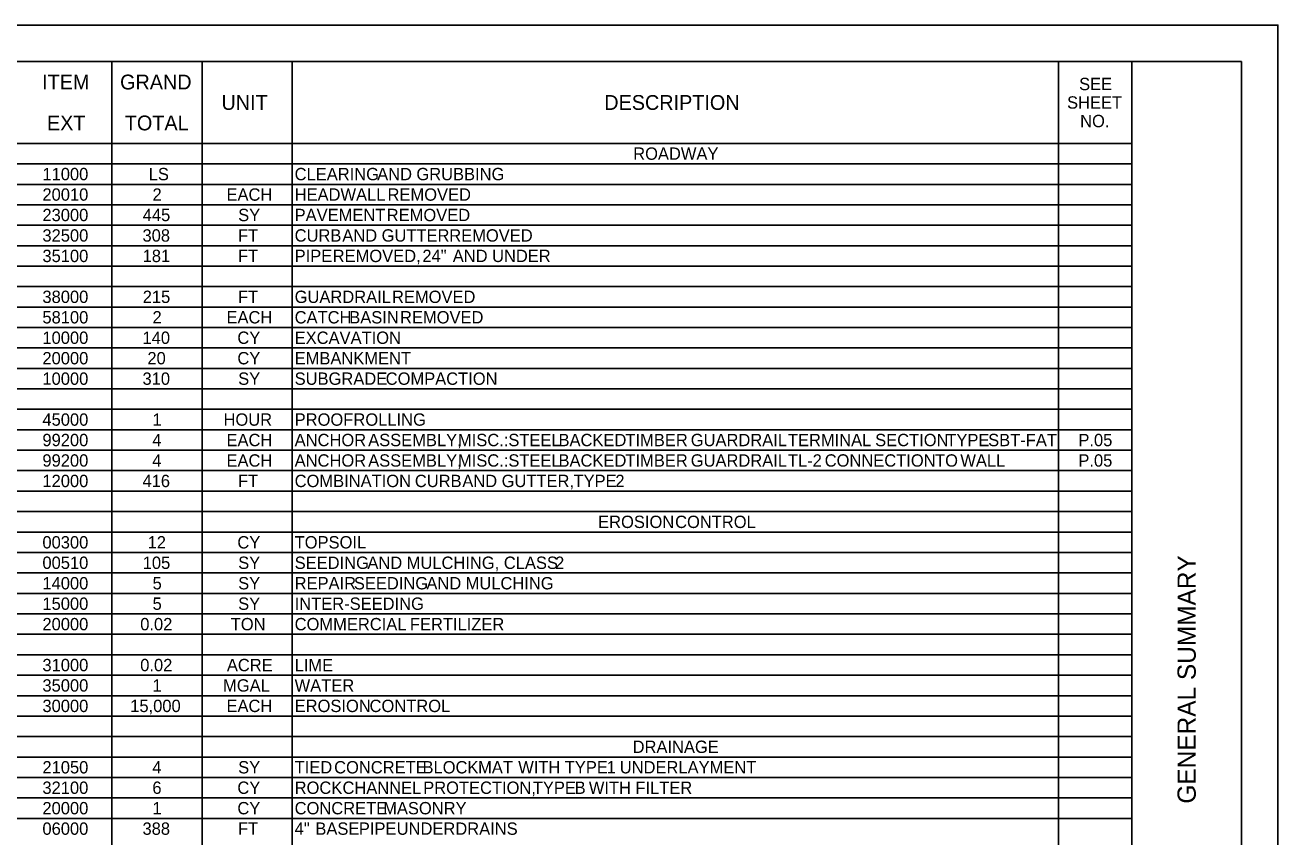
# Model space of a CAD drawing. Extents: x 0 to 34, y 0 to 22.
# Drawn here: x 16.85 to 34, y 10.89 to 22 of the extents above; entities that cross this region are included whole.
import ezdxf

# ---------------------------------------------------------------- set-up
doc = ezdxf.new("R2010")
doc.units = 0
for name, color, linetype in [('SH_Border', 7, 'Continuous'), ('SH_Cut_Line', 7, 'Continuous'), ('SH_Data', 7, 'Continuous')]:
    doc.layers.add(name, color=color, linetype=linetype)

msp = doc.modelspace()

# ---------------------------------------------------------------- linework, layer by layer
at = {"layer": 'SH_Border'}
msp.add_line((32, 0.5), (32, 21.5), dxfattribs=at)
msp.add_lwpolyline([(1.5, 21.5), (33.5, 21.5), (33.5, 0.5), (1.5, 0.5)], close=True, dxfattribs=at)
at = {"layer": 'SH_Cut_Line'}
msp.add_lwpolyline([(0, 0), (34, 0), (34, 22), (0, 22)], close=True, dxfattribs=at)
at = {"layer": 'SH_Data'}
for p, q in [((16.799, 21.5), (19.27, 21.5)), ((18.035, 0.502), (18.035, 21.5)), ((19.27, 21.5), (20.505, 21.5)), ((19.27, 0.502), (19.27, 21.5)), ((20.505, 21.5), (30.995, 21.5)), ((20.505, 0.502), (20.505, 21.5)), ((30.995, 21.5), (32, 21.5)), ((30.995, 0.502), (30.995, 21.5)), ((32, 0.502), (32, 21.5)), ((13.555, 20.38), (32, 20.38)), ((19.27, 20.38), (32, 20.38)), ((1.5, 20.1), (32, 20.1)), ((1.5, 19.82), (32, 19.82)), ((1.5, 19.54), (32, 19.54)), ((1.5, 19.26), (32, 19.26)), ((1.5, 18.98), (32, 18.98)), ((1.5, 18.7), (32, 18.7)), ((1.5, 18.42), (32, 18.42)), ((1.5, 18.14), (32, 18.14)), ((1.5, 17.86), (32, 17.86)), ((1.5, 17.58), (32, 17.58)), ((1.5, 17.3), (32, 17.3)), ((1.5, 17.021), (32, 17.021)), ((1.5, 16.741), (32, 16.741)), ((1.5, 16.461), (32, 16.461)), ((1.5, 16.181), (32, 16.181)), ((1.5, 15.901), (32, 15.901)), ((1.5, 15.621), (32, 15.621)), ((1.5, 15.341), (32, 15.341)), ((1.5, 15.061), (32, 15.061)), ((1.5, 14.781), (32, 14.781)), ((1.5, 14.501), (32, 14.501)), ((1.5, 14.221), (32, 14.221)), ((1.5, 13.941), (32, 13.941)), ((1.5, 13.661), (32, 13.661)), ((1.5, 13.381), (32, 13.381)), ((1.5, 13.101), (32, 13.101)), ((1.5, 12.821), (32, 12.821)), ((1.5, 12.541), (32, 12.541)), ((1.5, 12.261), (32, 12.261)), ((1.5, 11.981), (32, 11.981)), ((1.5, 11.701), (32, 11.701)), ((1.5, 11.421), (32, 11.421)), ((1.5, 11.141), (32, 11.141))]:
    msp.add_line(p, q, dxfattribs=at)

# ---------------------------------------------------------------- texts
for s, height, p in [('ITEM', 0.2027, (17.081, 21.119)), ('GRAND', 0.2027, (18.148, 21.119)), ('SEE', 0.1689, (31.278, 21.109)), ('UNIT', 0.2027, (19.536, 20.839)), ('DESCRIPTION', 0.20269, (24.777, 20.839)), ('SHEET', 0.1689, (31.113, 20.856)), ('EXT', 0.2027, (17.147, 20.559)), ('TOTAL', 0.2027, (18.213, 20.559)), ('NO.', 0.1689, (31.292, 20.602)), ('ROADWAY', 0.1689, (25.173, 20.156)), ('11000', 0.1689, (17.085, 19.876)), ('LS', 0.1689, (18.54, 19.876)), ('CLEARING', 0.1689, (20.538, 19.876)), (' AND', 0.1689, (21.605, 19.876)), (' GRUBBING', 0.1689, (22.142, 19.876)), ('20010', 0.1689, (17.085, 19.596)), ('2', 0.169, (18.592, 19.596)), ('EACH', 0.1689, (19.605, 19.596)), ('HEADWALL', 0.1689, (20.538, 19.596)), (' REMOVED', 0.1689, (21.747, 19.596)), ('23000', 0.1689, (17.085, 19.316)), ('445', 0.1689, (18.458, 19.316)), ('SY', 0.1689, (19.765, 19.316)), ('PAVEMENT', 0.1689, (20.538, 19.316)), (' REMOVED', 0.1689, (21.736, 19.316)), ('32500', 0.1689, (17.085, 19.036)), ('308', 0.1689, (18.455, 19.036)), ('FT', 0.1689, (19.762, 19.036)), ('CURB', 0.1689, (20.538, 19.036)), (' AND', 0.1689, (21.128, 19.036)), (' GUTTER', 0.1689, (21.666, 19.036)), (' REMOVED', 0.1689, (22.592, 19.036)), ('35100', 0.1689, (17.085, 18.756)), ('181', 0.1689, (18.457, 18.756)), ('FT', 0.1689, (19.762, 18.756)), ('PIPE', 0.1689, (20.538, 18.756)), (' REMOVED,', 0.1689, (20.996, 18.756)), (' 24"', 0.1689, (22.224, 18.756)), (' AND', 0.1689, (22.64, 18.756)), (' UNDER', 0.1689, (23.178, 18.756)), ('38000', 0.1689, (17.085, 18.196)), ('215', 0.1689, (18.458, 18.196)), ('FT', 0.1689, (19.762, 18.196)), ('GUARDRAIL', 0.1689, (20.538, 18.196)), (' REMOVED', 0.1689, (21.808, 18.196)), ('58100', 0.1689, (17.085, 17.916)), ('2', 0.169, (18.592, 17.916)), ('EACH', 0.1689, (19.605, 17.916)), ('CATCH', 0.1689, (20.538, 17.916)), (' BASIN', 0.1689, (21.223, 17.916)), (' REMOVED', 0.1689, (21.918, 17.916)), ('10000', 0.1689, (17.085, 17.636)), ('140', 0.1689, (18.455, 17.636)), ('CY', 0.1689, (19.754, 17.636)), ('EXCAVATION', 0.1689, (20.538, 17.636)), ('20000', 0.1689, (17.085, 17.356)), ('20', 0.1689, (18.522, 17.356)), ('CY', 0.1689, (19.754, 17.356)), ('EMBANKMENT', 0.1689, (20.538, 17.356)), ('10000', 0.1689, (17.085, 17.076)), ('310', 0.1689, (18.455, 17.076)), ('SY', 0.1689, (19.765, 17.076)), ('SUBGRADE', 0.1689, (20.538, 17.076)), (' COMPACTION', 0.16891, (21.722, 17.076)), ('45000', 0.1689, (17.085, 16.516)), ('1', 0.169, (18.592, 16.516)), ('HOUR', 0.1689, (19.564, 16.516)), ('PROOF', 0.1689, (20.538, 16.516)), (' ROLLING', 0.1689, (21.28, 16.516)), ('99200', 0.1689, (17.085, 16.236)), ('4', 0.169, (18.589, 16.236)), ('EACH', 0.1689, (19.605, 16.236)), ('ANCHOR', 0.1689, (20.538, 16.236)), (' ASSEMBLY,', 0.1689, (21.482, 16.236)), (' MISC.:STEEL', 0.16891, (22.711, 16.236)), (' BACKED', 0.1689, (24.088, 16.236)), (' TIMBER', 0.1689, (25.004, 16.236)), (' GUARDRAIL', 0.1689, (25.898, 16.236)), (' TERMINAL', 0.1689, (27.228, 16.236)), (' SECTION', 0.1689, (28.423, 16.236)), (' TYPE', 0.1689, (29.397, 16.236)), (' SBT-FAT', 0.1689, (29.97, 16.236)), ('P.05', 0.1689, (31.268, 16.236)), ('99200', 0.1689, (17.085, 15.956)), ('4', 0.169, (18.589, 15.956)), ('EACH', 0.1689, (19.605, 15.956)), ('ANCHOR', 0.1689, (20.538, 15.956)), (' ASSEMBLY,', 0.1689, (21.482, 15.956)), (' MISC.:STEEL', 0.16891, (22.711, 15.956)), (' BACKED', 0.1689, (24.088, 15.956)), (' TIMBER', 0.1689, (25.004, 15.956)), (' GUARDRAIL', 0.1689, (25.898, 15.956)), (' TL-2', 0.1689, (27.228, 15.956)), (' CONNECTION', 0.16891, (27.732, 15.956)), (' TO', 0.1689, (29.243, 15.956)), (' WALL', 0.1689, (29.589, 15.956)), ('P.05', 0.1689, (31.268, 15.956)), ('12000', 0.1689, (17.085, 15.676)), ('416', 0.1689, (18.455, 15.676)), ('FT', 0.1689, (19.762, 15.676)), ('COMBINATION', 0.16891, (20.538, 15.676)), (' CURB', 0.1689, (22.121, 15.676)), (' AND', 0.1689, (22.771, 15.676)), (' GUTTER,', 0.1689, (23.309, 15.676)), (' TYPE', 0.1689, (24.293, 15.676)), (' 2', 0.1689, (24.866, 15.676)), ('EROSION', 0.1689, (24.693, 15.116)), (' CONTROL', 0.1689, (25.684, 15.116)), ('00300', 0.1689, (17.085, 14.836)), ('12', 0.1689, (18.525, 14.836)), ('CY', 0.1689, (19.754, 14.836)), ('TOPSOIL', 0.1689, (20.538, 14.836)), ('00510', 0.1689, (17.085, 14.556)), ('105', 0.1689, (18.458, 14.556)), ('SY', 0.1689, (19.765, 14.556)), ('SEEDING', 0.1689, (20.538, 14.556)), (' AND', 0.1689, (21.471, 14.556)), (' MULCHING,', 0.1689, (22.009, 14.556)), (' CLASS', 0.1689, (23.339, 14.556)), (' 2', 0.1689, (24.041, 14.556)), ('14000', 0.1689, (17.085, 14.276)), ('5', 0.169, (18.593, 14.276)), ('SY', 0.1689, (19.765, 14.276)), ('REPAIR', 0.1689, (20.538, 14.276)), (' SEEDING', 0.1689, (21.286, 14.276)), (' AND', 0.1689, (22.279, 14.276)), (' MULCHING', 0.1689, (22.816, 14.276)), ('15000', 0.1689, (17.085, 13.996)), ('5', 0.169, (18.593, 13.996)), ('SY', 0.1689, (19.765, 13.996)), ('INTER-SEEDING', 0.16891, (20.538, 13.996)), ('20000', 0.1689, (17.085, 13.716)), ('0.02', 0.1689, (18.424, 13.716)), ('TON', 0.1689, (19.663, 13.716)), ('COMMERCIAL', 0.1689, (20.538, 13.716)), (' FERTILIZER', 0.16891, (22.053, 13.716)), ('31000', 0.1689, (17.085, 13.156)), ('0.02', 0.1689, (18.424, 13.156)), ('ACRE', 0.1689, (19.61, 13.156)), ('LIME', 0.1689, (20.538, 13.156)), ('35000', 0.1689, (17.085, 12.877)), ('1', 0.169, (18.592, 12.877)), ('MGAL', 0.1689, (19.558, 12.877)), ('WATER', 0.1689, (20.538, 12.877)), ('30000', 0.1689, (17.085, 12.597)), ('15,000', 0.1689, (18.287, 12.597)), ('EACH', 0.1689, (19.605, 12.597)), ('EROSION', 0.1689, (20.538, 12.597)), (' CONTROL', 0.1689, (21.501, 12.597)), ('DRAINAGE', 0.1689, (25.165, 12.037)), ('21050', 0.1689, (17.085, 11.757)), ('4', 0.169, (18.589, 11.757)), ('SY', 0.1689, (19.765, 11.757)), ('TIED', 0.1689, (20.538, 11.757)), (' CONCRETE', 0.1689, (21.016, 11.757)), (' BLOCK', 0.1689, (22.226, 11.757)), (' MAT', 0.1689, (22.987, 11.757)), (' WITH', 0.1689, (23.536, 11.757)), (' TYPE', 0.1689, (24.173, 11.757)), (' 1', 0.1689, (24.746, 11.757)), (' UNDERLAYMENT', 0.16891, (24.926, 11.757)), ('32100', 0.1689, (17.085, 11.477)), ('6', 0.169, (18.59, 11.477)), ('CY', 0.1689, (19.754, 11.477)), ('ROCK', 0.1689, (20.538, 11.477)), (' CHANNEL', 0.1689, (21.13, 11.477)), (' PROTECTION,', 0.16891, (22.235, 11.477)), (' TYPE', 0.1689, (23.736, 11.477)), (' B', 0.1689, (24.309, 11.477)), (' WITH', 0.1689, (24.503, 11.477)), (' FILTER', 0.1689, (25.14, 11.477)), ('20000', 0.1689, (17.085, 11.197)), ('1', 0.169, (18.592, 11.197)), ('CY', 0.1689, (19.754, 11.197)), ('CONCRETE', 0.1689, (20.538, 11.197)), (' MASONRY', 0.1689, (21.687, 11.197)), ('06000', 0.1689, (17.085, 10.917)), ('388', 0.1689, (18.455, 10.917)), ('FT', 0.1689, (19.762, 10.917)), ('4"', 0.1689, (20.538, 10.917)), (' BASE', 0.1689, (20.759, 10.917)), (' PIPE', 0.1689, (21.354, 10.917)), (' UNDERDRAINS', 0.16891, (21.872, 10.917))]:
    msp.add_text(s, height=height, dxfattribs=at).set_placement(p)
msp.add_text('GENERAL SUMMARY', height=0.25, rotation=90, dxfattribs=at).set_placement((32.875, 11.344))

doc.saveas('drawing.dxf')
